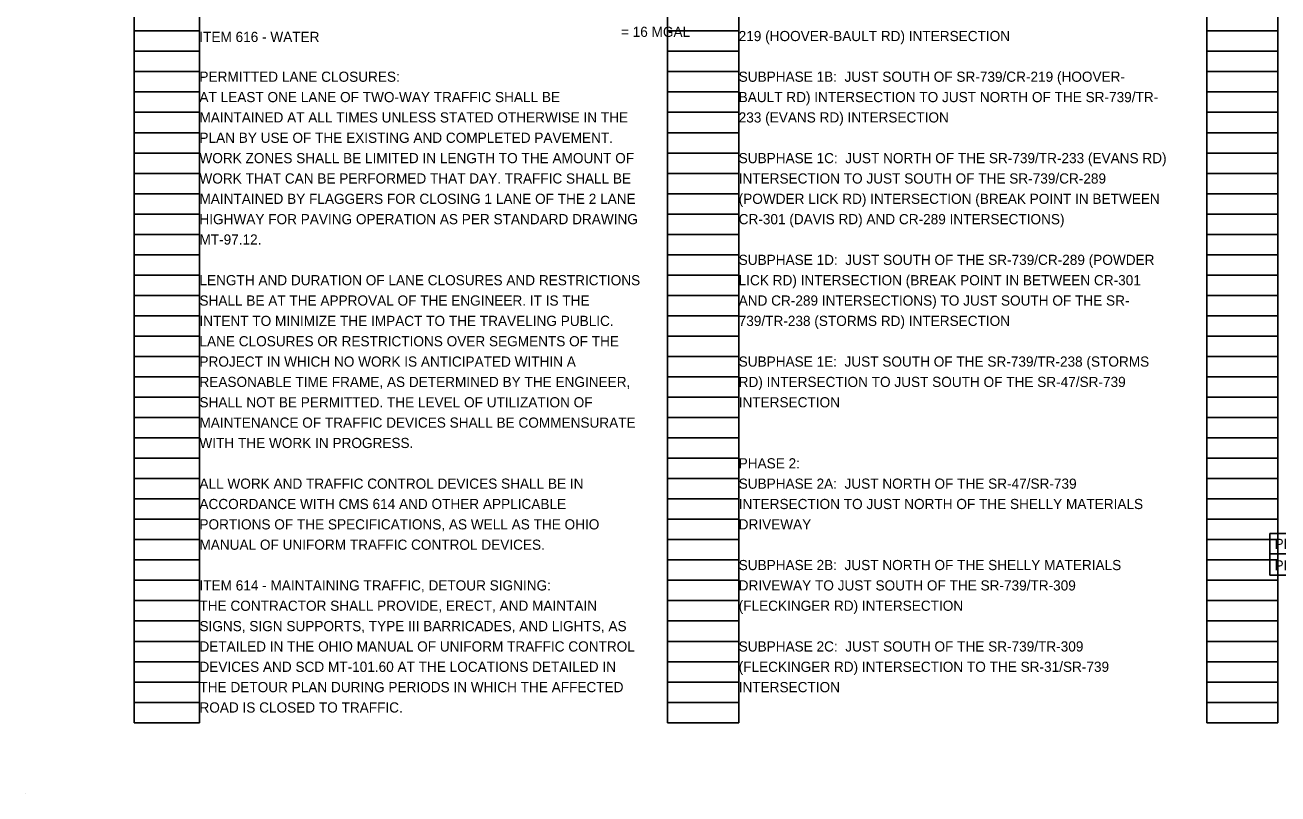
# Model space of a CAD drawing. Extents: x 63 to 145.9, y -75 to 21.1.
# Drawn here: x 62.97 to 80.21, y -25 to -14.42 of the extents above; entities that cross this region are included whole.
import ezdxf

# ---------------------------------------------------------------- set-up
doc = ezdxf.new("R2010")
doc.units = 0
doc.layers.add('AP_P_Airside', color=7, linetype='Continuous')
doc.layers.add('SH_Text', color=7, linetype='Continuous')

msp = doc.modelspace()

# ---------------------------------------------------------------- linework, layer by layer
at = {"layer": 'AP_P_Airside'}
for p, q in [((80.094, -21.414), (86.584, -21.414)), ((80.094, -21.414), (80.094, -21.991)), ((80.094, -21.694), (86.584, -21.694)), ((80.094, -21.991), (84.772, -21.991))]:
    msp.add_line(p, q, dxfattribs=at)
at = {"layer": 'SH_Text'}
for p, q in [((64.466, -24.02), (64.466, -3.86)), ((65.366, -24.02), (65.366, -3.86)), ((71.806, -24.02), (71.806, -3.86)), ((72.786, -24.02), (72.786, -3.86)), ((79.226, -24.02), (79.226, -3.86)), ((80.206, -24.02), (80.206, -3.86)), ((64.466, -14.5), (65.366, -14.5)), ((71.806, -14.5), (72.786, -14.5)), ((79.226, -14.5), (80.206, -14.5)), ((64.466, -14.78), (65.366, -14.78)), ((71.806, -14.78), (72.786, -14.78)), ((79.226, -14.78), (80.206, -14.78)), ((64.466, -15.06), (65.366, -15.06)), ((71.806, -15.06), (72.786, -15.06)), ((79.226, -15.06), (80.206, -15.06)), ((64.466, -15.34), (65.366, -15.34)), ((71.806, -15.34), (72.786, -15.34)), ((79.226, -15.34), (80.206, -15.34)), ((64.466, -15.62), (65.366, -15.62)), ((71.806, -15.62), (72.786, -15.62)), ((79.226, -15.62), (80.206, -15.62)), ((64.466, -15.9), (65.366, -15.9)), ((71.806, -15.9), (72.786, -15.9)), ((79.226, -15.9), (80.206, -15.9)), ((64.466, -16.18), (65.366, -16.18)), ((71.806, -16.18), (72.786, -16.18)), ((79.226, -16.18), (80.206, -16.18)), ((64.466, -16.46), (65.366, -16.46)), ((71.806, -16.46), (72.786, -16.46)), ((79.226, -16.46), (80.206, -16.46)), ((64.466, -16.74), (65.366, -16.74)), ((71.806, -16.74), (72.786, -16.74)), ((79.226, -16.74), (80.206, -16.74)), ((64.466, -17.02), (65.366, -17.02)), ((71.806, -17.02), (72.786, -17.02)), ((79.226, -17.02), (80.206, -17.02)), ((64.466, -17.3), (65.366, -17.3)), ((71.806, -17.3), (72.786, -17.3)), ((79.226, -17.3), (80.206, -17.3)), ((64.466, -17.58), (65.366, -17.58)), ((71.806, -17.58), (72.786, -17.58)), ((79.226, -17.58), (80.206, -17.58)), ((64.466, -17.86), (65.366, -17.86)), ((71.806, -17.86), (72.786, -17.86)), ((79.226, -17.86), (80.206, -17.86)), ((64.466, -18.14), (65.366, -18.14)), ((71.806, -18.14), (72.786, -18.14)), ((79.226, -18.14), (80.206, -18.14)), ((64.466, -18.42), (65.366, -18.42)), ((71.806, -18.42), (72.786, -18.42)), ((79.226, -18.42), (80.206, -18.42)), ((64.466, -18.7), (65.366, -18.7)), ((71.806, -18.7), (72.786, -18.7)), ((79.226, -18.7), (80.206, -18.7)), ((64.466, -18.98), (65.366, -18.98)), ((71.806, -18.98), (72.786, -18.98)), ((79.226, -18.98), (80.206, -18.98)), ((64.466, -19.26), (65.366, -19.26)), ((71.806, -19.26), (72.786, -19.26)), ((79.226, -19.26), (80.206, -19.26)), ((64.466, -19.54), (65.366, -19.54)), ((71.806, -19.54), (72.786, -19.54)), ((79.226, -19.54), (80.206, -19.54)), ((64.466, -19.82), (65.366, -19.82)), ((71.806, -19.82), (72.786, -19.82)), ((79.226, -19.82), (80.206, -19.82)), ((64.466, -20.1), (65.366, -20.1)), ((71.806, -20.1), (72.786, -20.1)), ((79.226, -20.1), (80.206, -20.1)), ((64.466, -20.38), (65.366, -20.38)), ((71.806, -20.38), (72.786, -20.38)), ((79.226, -20.38), (80.206, -20.38)), ((64.466, -20.66), (65.366, -20.66)), ((71.806, -20.66), (72.786, -20.66)), ((79.226, -20.66), (80.206, -20.66)), ((64.466, -20.94), (65.366, -20.94)), ((71.806, -20.94), (72.786, -20.94)), ((79.226, -20.94), (80.206, -20.94)), ((64.466, -21.22), (65.366, -21.22)), ((71.806, -21.22), (72.786, -21.22)), ((79.226, -21.22), (80.206, -21.22)), ((64.466, -21.5), (65.366, -21.5)), ((71.806, -21.5), (72.786, -21.5)), ((79.226, -21.5), (80.206, -21.5)), ((64.466, -21.78), (65.366, -21.78)), ((71.806, -21.78), (72.786, -21.78)), ((79.226, -21.78), (80.206, -21.78)), ((64.466, -22.06), (65.366, -22.06)), ((71.806, -22.06), (72.786, -22.06)), ((79.226, -22.06), (80.206, -22.06)), ((64.466, -22.34), (65.366, -22.34)), ((71.806, -22.34), (72.786, -22.34)), ((79.226, -22.34), (80.206, -22.34)), ((64.466, -22.62), (65.366, -22.62)), ((71.806, -22.62), (72.786, -22.62)), ((79.226, -22.62), (80.206, -22.62)), ((64.466, -22.9), (65.366, -22.9)), ((71.806, -22.9), (72.786, -22.9)), ((79.226, -22.9), (80.206, -22.9)), ((64.466, -23.18), (65.366, -23.18)), ((71.806, -23.18), (72.786, -23.18)), ((79.226, -23.18), (80.206, -23.18)), ((64.466, -23.46), (65.366, -23.46)), ((71.806, -23.46), (72.786, -23.46)), ((79.226, -23.46), (80.206, -23.46)), ((64.466, -23.74), (65.366, -23.74)), ((71.806, -23.74), (72.786, -23.74)), ((79.226, -23.74), (80.206, -23.74)), ((64.466, -24.02), (65.366, -24.02)), ((71.806, -24.02), (72.786, -24.02)), ((79.226, -24.02), (80.206, -24.02)), ((62.966, -25), (62.966, -25))]:
    msp.add_line(p, q, dxfattribs=at)

# ---------------------------------------------------------------- texts
at = {"layer": 'AP_P_Airside'}
for s, p in [('= 16 MGAL', (71.166, -14.582)), ('ITEM 616 - WATER', (65.364, -14.652)), ('219 (HOOVER-BAULT RD) INTERSECTION', (72.786, -14.64)), ('PERMITTED LANE CLOSURES:', (65.366, -15.2)), ('SUBPHASE 1B:  JUST SOUTH OF SR-739/CR-219 (HOOVER-', (72.786, -15.2)), ('AT LEAST ONE LANE OF TWO-WAY TRAFFIC SHALL BE ', (65.366, -15.48)), ('BAULT RD) INTERSECTION TO JUST NORTH OF THE SR-739/TR-', (72.786, -15.48)), ('MAINTAINED AT ALL TIMES UNLESS STATED OTHERWISE IN THE ', (65.366, -15.76)), ('233 (EVANS RD) INTERSECTION ', (72.786, -15.76)), ('PLAN BY USE OF THE EXISTING AND COMPLETED PAVEMENT. ', (65.366, -16.04)), ('WORK ZONES SHALL BE LIMITED IN LENGTH TO THE AMOUNT OF ', (65.366, -16.32)), ('SUBPHASE 1C:  JUST NORTH OF THE SR-739/TR-233 (EVANS RD)  ', (72.786, -16.32)), ('WORK THAT CAN BE PERFORMED THAT DAY. TRAFFIC SHALL BE ', (65.366, -16.6)), ('INTERSECTION TO JUST SOUTH OF THE SR-739/CR-289 ', (72.786, -16.6)), ('MAINTAINED BY FLAGGERS FOR CLOSING 1 LANE OF THE 2 LANE ', (65.366, -16.88)), ('(POWDER LICK RD) INTERSECTION (BREAK POINT IN BETWEEN ', (72.786, -16.88)), ('HIGHWAY FOR PAVING OPERATION AS PER STANDARD DRAWING ', (65.366, -17.16)), ('CR-301 (DAVIS RD) AND CR-289 INTERSECTIONS)', (72.786, -17.16)), ('MT-97.12. ', (65.366, -17.44)), ('SUBPHASE 1D:  JUST SOUTH OF THE SR-739/CR-289 (POWDER ', (72.786, -17.72)), ('LENGTH AND DURATION OF LANE CLOSURES AND RESTRICTIONS ', (65.366, -18)), ('LICK RD) INTERSECTION (BREAK POINT IN BETWEEN CR-301 ', (72.786, -18)), ('SHALL BE AT THE APPROVAL OF THE ENGINEER. IT IS THE ', (65.366, -18.28)), ('AND CR-289 INTERSECTIONS) TO JUST SOUTH OF THE SR-', (72.786, -18.28)), ('INTENT TO MINIMIZE THE IMPACT TO THE TRAVELING PUBLIC. ', (65.366, -18.56)), ('739/TR-238 (STORMS RD) INTERSECTION', (72.786, -18.56)), ('LANE CLOSURES OR RESTRICTIONS OVER SEGMENTS OF THE ', (65.366, -18.84)), ('PROJECT IN WHICH NO WORK IS ANTICIPATED WITHIN A ', (65.366, -19.12)), ('SUBPHASE 1E:  JUST SOUTH OF THE SR-739/TR-238 (STORMS ', (72.786, -19.12)), ('REASONABLE TIME FRAME, AS DETERMINED BY THE ENGINEER, ', (65.366, -19.4)), ('RD) INTERSECTION TO JUST SOUTH OF THE SR-47/SR-739 ', (72.786, -19.4)), ('SHALL NOT BE PERMITTED. THE LEVEL OF UTILIZATION OF ', (65.366, -19.68)), ('INTERSECTION', (72.786, -19.68)), ('MAINTENANCE OF TRAFFIC DEVICES SHALL BE COMMENSURATE ', (65.366, -19.96)), ('WITH THE WORK IN PROGRESS.', (65.366, -20.24)), ('PHASE 2: ', (72.786, -20.52)), ('ALL WORK AND TRAFFIC CONTROL DEVICES SHALL BE IN ', (65.366, -20.8)), ('SUBPHASE 2A:  JUST NORTH OF THE SR-47/SR-739 ', (72.786, -20.8)), ('ACCORDANCE WITH CMS 614 AND OTHER APPLICABLE ', (65.366, -21.08)), ('INTERSECTION TO JUST NORTH OF THE SHELLY MATERIALS ', (72.786, -21.08)), ('PORTIONS OF THE SPECIFICATIONS, AS WELL AS THE OHIO ', (65.366, -21.36)), ('DRIVEWAY', (72.786, -21.36)), ('MANUAL OF UNIFORM TRAFFIC CONTROL DEVICES.', (65.366, -21.64)), ('PHASE 1', (80.16, -21.628)), ('SUBPHASE 2B:  JUST NORTH OF THE SHELLY MATERIALS ', (72.786, -21.92)), ('PHASE 2', (80.16, -21.925)), ('ITEM 614 - MAINTAINING TRAFFIC, DETOUR SIGNING:', (65.366, -22.2)), ('DRIVEWAY TO JUST SOUTH OF THE SR-739/TR-309 ', (72.786, -22.2)), ('THE CONTRACTOR SHALL PROVIDE, ERECT, AND MAINTAIN ', (65.366, -22.48)), ('(FLECKINGER RD) INTERSECTION', (72.786, -22.48)), ('SIGNS, SIGN SUPPORTS, TYPE III BARRICADES, AND LIGHTS, AS ', (65.366, -22.76)), ('DETAILED IN THE OHIO MANUAL OF UNIFORM TRAFFIC CONTROL ', (65.366, -23.04)), ('SUBPHASE 2C:  JUST SOUTH OF THE SR-739/TR-309 ', (72.786, -23.04)), ('DEVICES AND SCD MT-101.60 AT THE LOCATIONS DETAILED IN ', (65.366, -23.32)), ('(FLECKINGER RD) INTERSECTION TO THE SR-31/SR-739 ', (72.786, -23.32)), ('THE DETOUR PLAN DURING PERIODS IN WHICH THE AFFECTED ', (65.366, -23.6)), ('INTERSECTION', (72.786, -23.6)), ('ROAD IS CLOSED TO TRAFFIC.     ', (65.366, -23.88))]:
    msp.add_text(s, height=0.14, dxfattribs=at).set_placement(p)

doc.saveas('drawing.dxf')
